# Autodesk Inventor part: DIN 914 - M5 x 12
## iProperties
Created: 2006-02
Part Number: DIN 914 - M5 x 12
Material: Steel, Mild
Description: Hexagon Socket Set Screw
Document SubType Name: Modeling
Standard: DIN 914
Designer: Andy Moles
Standards Organization: DIN
Language: en-US
Size Designation: M5 x 10
Categories: <MemberInstance><Categories><Category DisplayName="Fasteners" InternalName="e4da775c-781d-43d5-af7c-5136215cf5a6" Mnemonic="FSTN"><Category DisplayName="Bolts"
Density: 1 g/cm^3
Author: Andy Moles
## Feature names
1. Body [Revolution]
2. Slot [Extrusion]
3. Chamfer1
4. Chamfer2
